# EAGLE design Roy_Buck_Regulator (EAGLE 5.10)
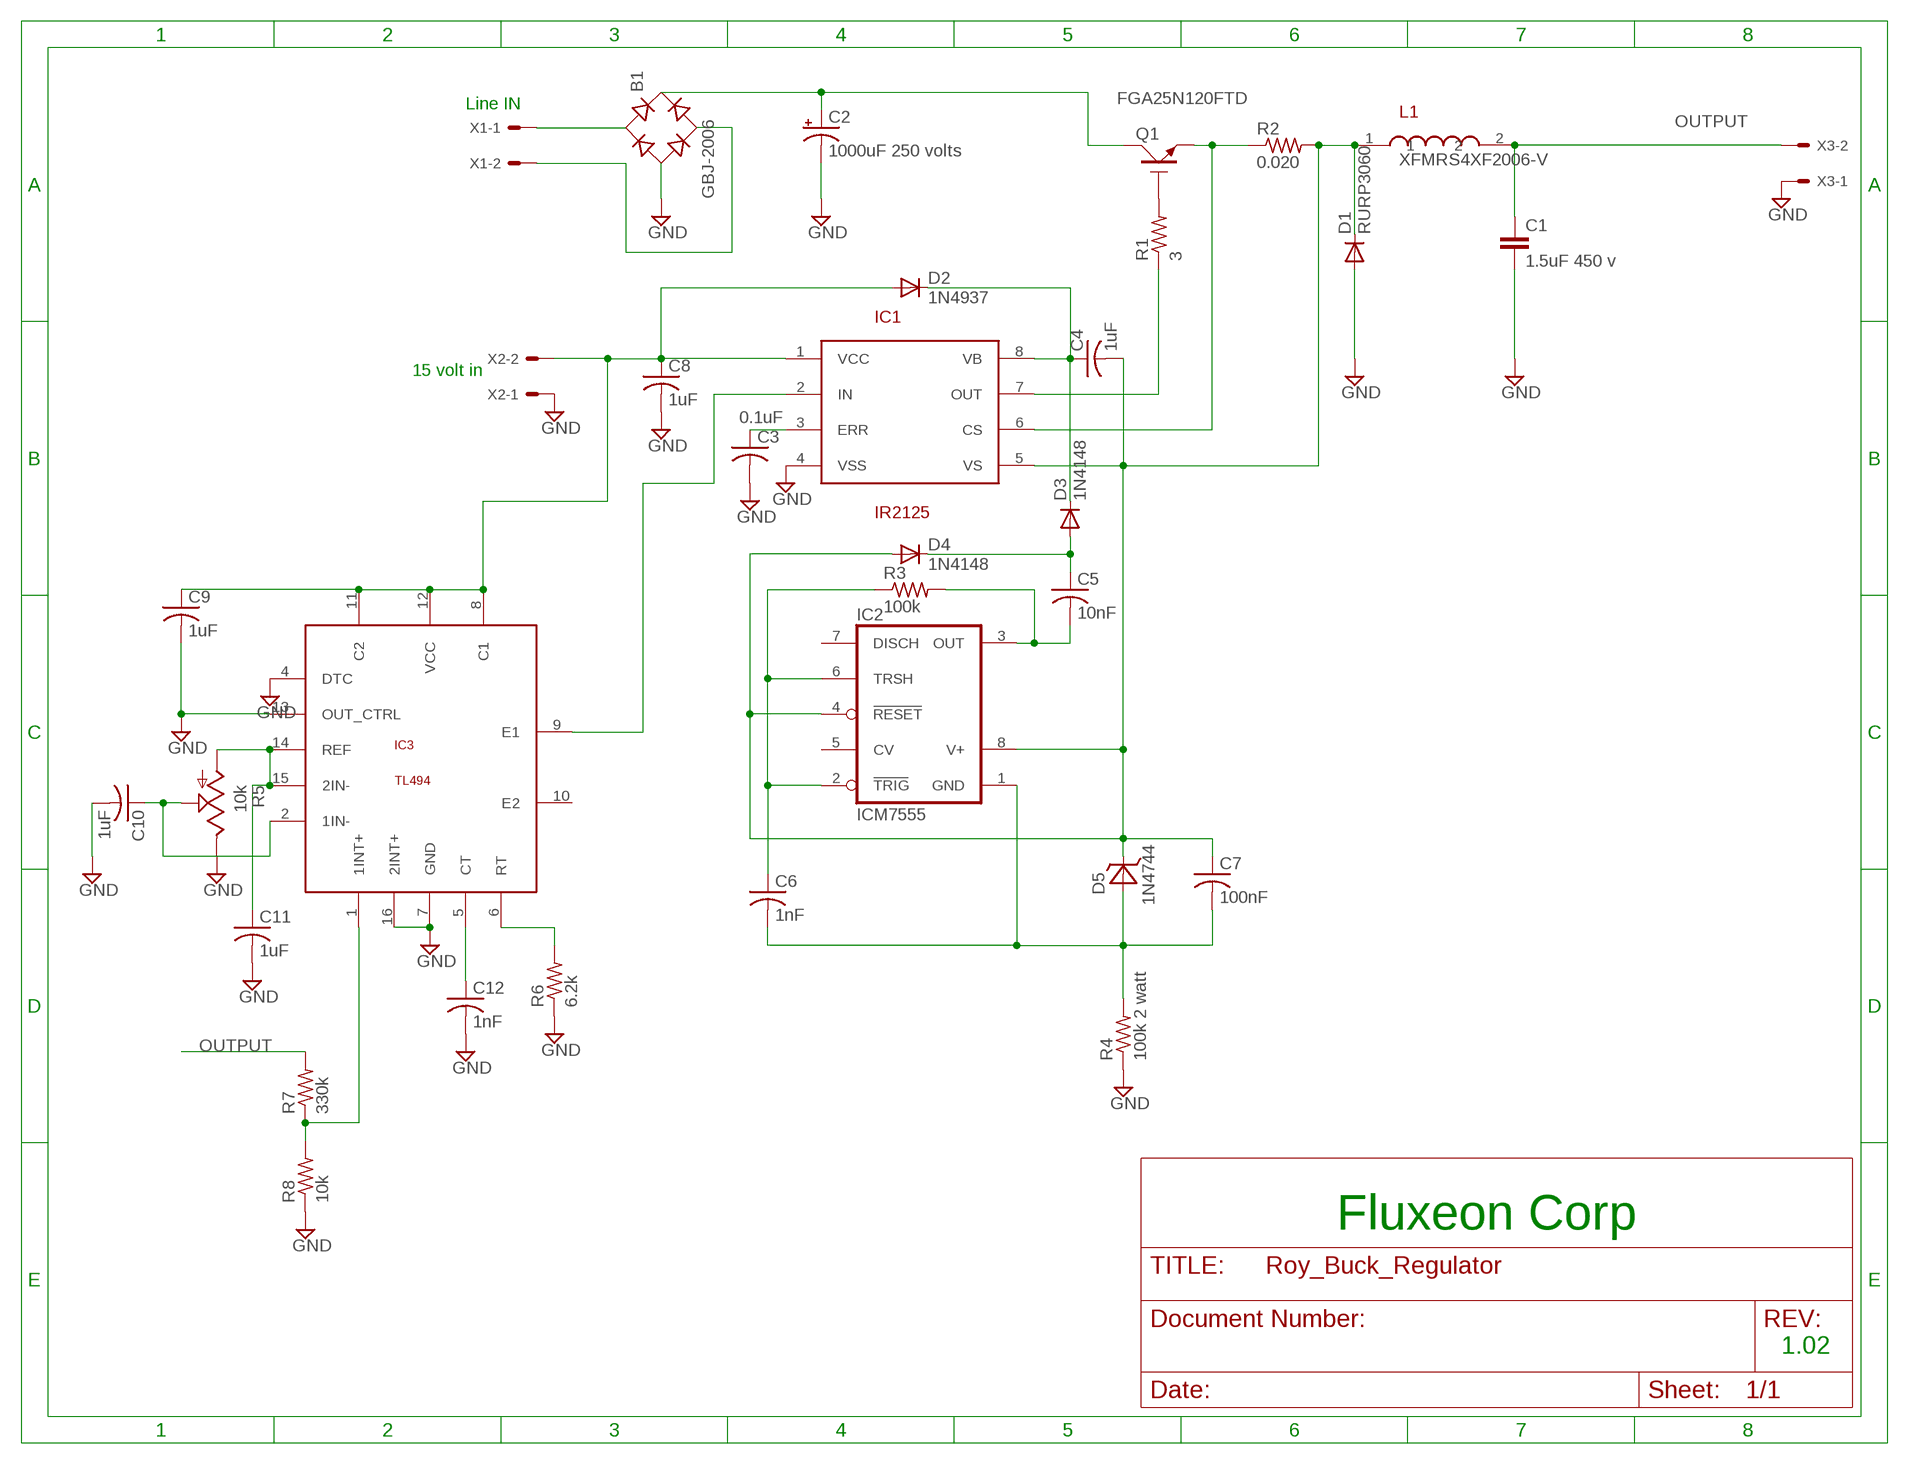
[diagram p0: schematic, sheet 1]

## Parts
B1  GBJ-2006  RECTIFIER-DSI32  [DSI32]
C1  1.5uF 450 v  CBLUE  [BLUE_1.5UF]
C2  1000uF 250 volts  CAP_1000UF_250VOLT  [ELECTRO_1_DIAMETER_10MM]
C3  0.1uF  C-US050-075X075  [C050-075X075]
C4  1uF  C-US050-075X075  [C050-075X075]
C5  10nF  C-US050-075X075  [C050-075X075]
C6  1nF  C-US050-075X075  [C050-075X075]
C7  100nF  C-US050-075X075  [C050-075X075]
C8  1uF  C-US050-075X075  [C050-075X075]
C9  1uF  C-US050-075X075  [C050-075X075]
C10  1uF  C-US050-075X075  [C050-075X075]
C11  1uF  C-US050-075X075  [C050-075X075]
C12  1nF  C-US050-075X075  [C050-075X075]
D1  RURP3060  RURP3060_DIODE"  [TO220ACS]
D2  1N4937  [DO41-10]
D3  1N4148  1N4148DO35-10  [DO35-10]
D4  1N4148  1N4148DO35-10  [DO35-10]
D5  1N4744  [DO41-10]
IC1  IR2125  IR2125_HI_SIDE_DRVRDIP8  [DIL08]
IC2  ICM7555  [DIL08]
IC3  TL494PDIP  [DIL16]
L1  XFMRS4XF2006-V  [TOROID_700]
Q1  FGA25N120FTD  [TO247BV]
R1  3  R-US_0617/17  [0617/17]
R2  0.020  R-US_0817/22  [CURRENT_SENSE_1.1_INCH_GRID]
R3  100k  R-US_0207/10  [0207/10]
R4  100k 2 watt  R-US_0414/15  [0414/15]
R5  10k  TRIM_US-10MM  [10MM_POT]
R6  6.2k  R-US_0207/10  [0207/10]
R7  330k  R-US_0207/10  [0207/10]
R8  10k  R-US_0207/10  [0207/10]
X1  KK-156-2  [KK-156-2]
X2  KK-156-2  [KK-156-2]
X3  KK-156-2  [KK-156-2]

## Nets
GND: B1.- C1.2 C2.2(-) C3.2 C8.2 C9.2 C10.2 C11.2 C12.2 D1.A IC1.4(VSS) IC3.4(DTC) IC3.7(GND) IC3.13(OUT_CTRL) IC3.16(2INT+) R4.1 R5.P$2(E) R6.1 R8.1 X2.1 X3.1
N$1: Q1.G R1.2
N$2: IC1.7(OUT) R1.1
N$3: C6.2 C7.2 D5.A IC2.1(GND) R4.2
N$4: IC3.1(1INT+) R7.1 R8.2
N$5 [high voltage]: B1.+ C2.1(+) Q1.D(C)
N$6 [high voltage]: B1.AC1 X1.1
N$7 [high voltage]: B1.AC2 X1.2
N$8 [high voltage]: IC1.6(CS) Q1.S(E) R2.1
N$9: C3.1 IC1.3(ERR)
N$10: C11.1 IC3.14(REF) IC3.15(2IN-) R5.P$3(A)
N$11: C4.1 D2.C D3.C IC1.8(VB)
N$14: C5.1 D3.A D4.C
N$15: C5.2 IC2.3(OUT) R3.2
N$16: C6.1 IC2.2(TRIG) IC2.6(TRSH) R3.1
N$17 [high voltage]: C4.2 C7.1 D1.C D4.A D5.C IC1.5(VS) IC2.4(RESET) IC2.8(V+) L1.1 R2.2
N$18: C10.1 IC3.2(1IN-) R5.P$1(S)
N$19: C12.1 IC3.5(CT)
N$20: IC3.6(RT) R6.2
N$21: IC1.2(IN) IC3.9(E1)
OUTPUT [high voltage]: C1.1 L1.2 R7.2 X3.2
VCC: C8.1 C9.1 D2.A IC1.1(VCC) IC3.8(C1) IC3.11(C2) IC3.12(VCC) X2.2
Unconnected: IC2.5(CV) IC2.7(DISCH) IC3.10(E2)

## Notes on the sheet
- Line IN
- 15 volt in
- Fluxeon Corp
- 1.02

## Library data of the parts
B1 = 00John:RECTIFIER-: Rectifier
C1 = 00John:C: CAPACITOR
C2 = 00John:CAP_1000UF_250VOLT: Electrolytic Capacitor, Snap-in
C3-C12 = 00John:C-US: CAPACITOR, American symbol
D1 = 00John:RURP3060_DIODE: 30 amp 600 volt ultrahigh speed soft recovery diode
D2 = 00John:1N4937: DIODE
D3 D4 = diode:1N4148: DIODE
D5 = 00John:1N4744: 1N4744 15 volt 1 watt Zener Diode
IC1 = 00John:IR2125_HI_SIDE_DRVR: IR2125 high side gate driver
IC2 = maxim:ICM7555: TIMER
IC3 = 00John:TL494: PWM Voltage Regulator/Controller
L1 = 00John:XFMRS4XF2006-V: Inductor, Toroidal, 200uH
Q1 = 00John:FGA25N120FTD: Fairchild FGA25n120 IGBT 1200 volts 50 amps TO-3P package
R1-R4 R6-R8 = 00John:R-US_: RESISTOR, American symbol
R5 = 00John:TRIM_US-: POTENTIOMETER
X1-X3 = 00John:KK-156-2: KK 156 HEADER

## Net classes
1 high voltage: width 2.54 mm, clearance 0.635 mm

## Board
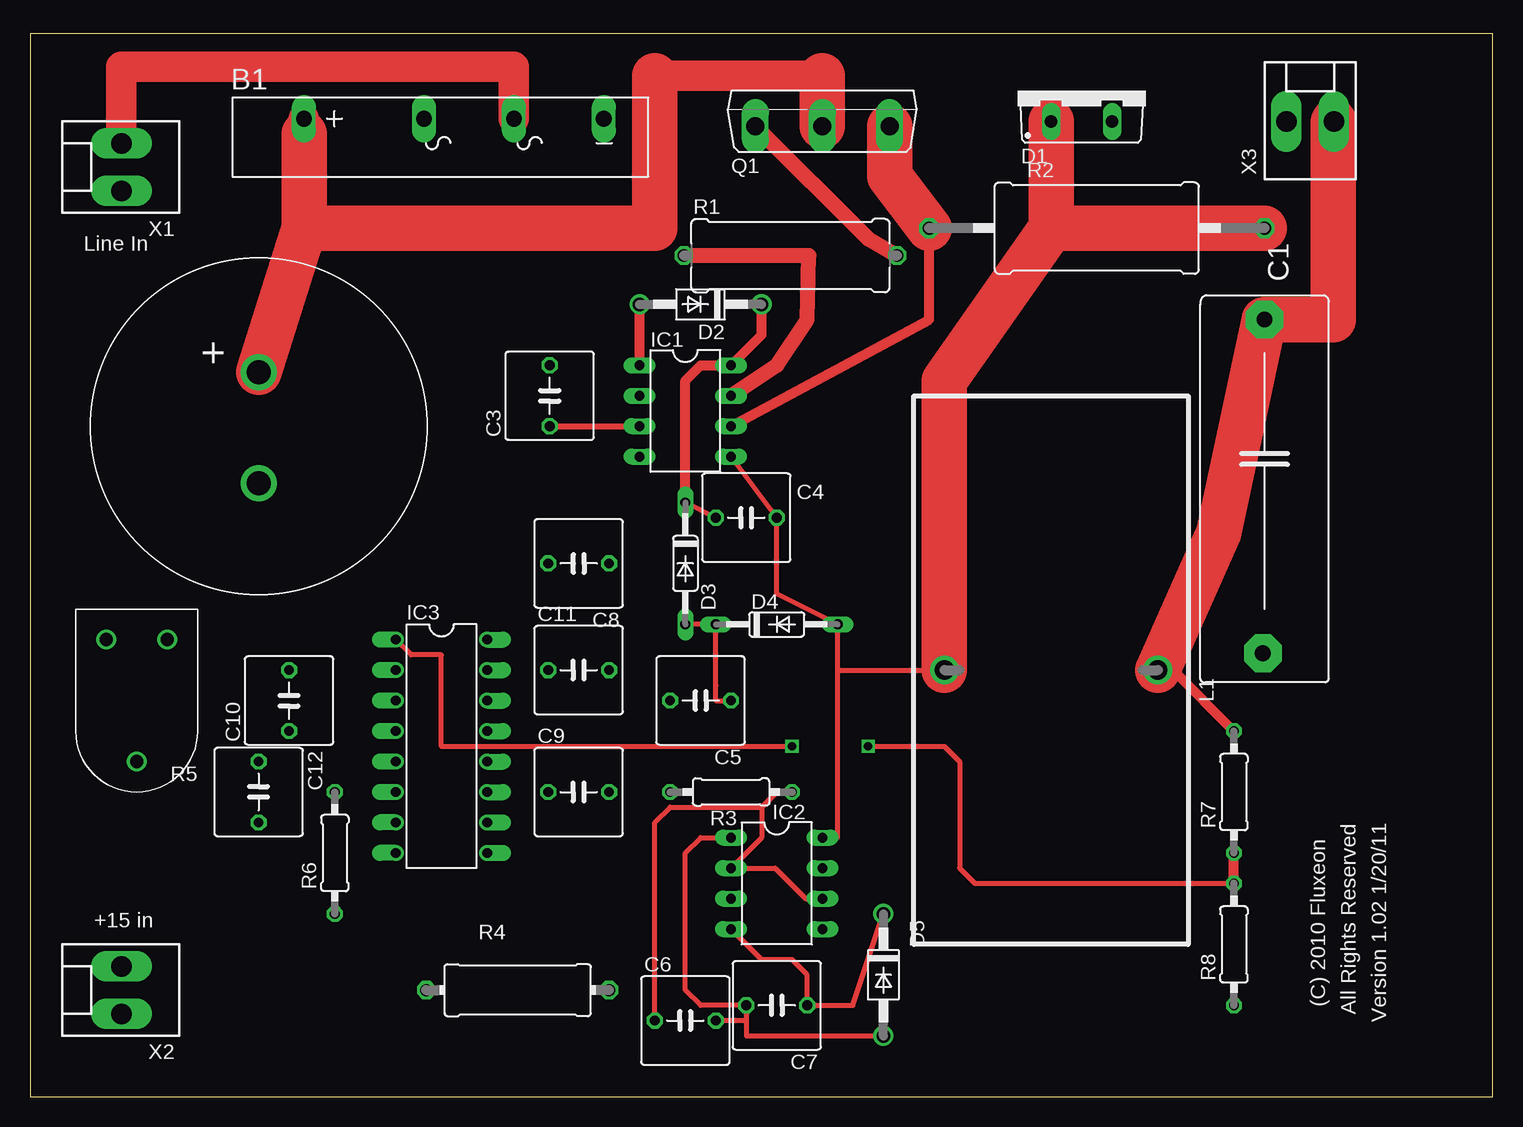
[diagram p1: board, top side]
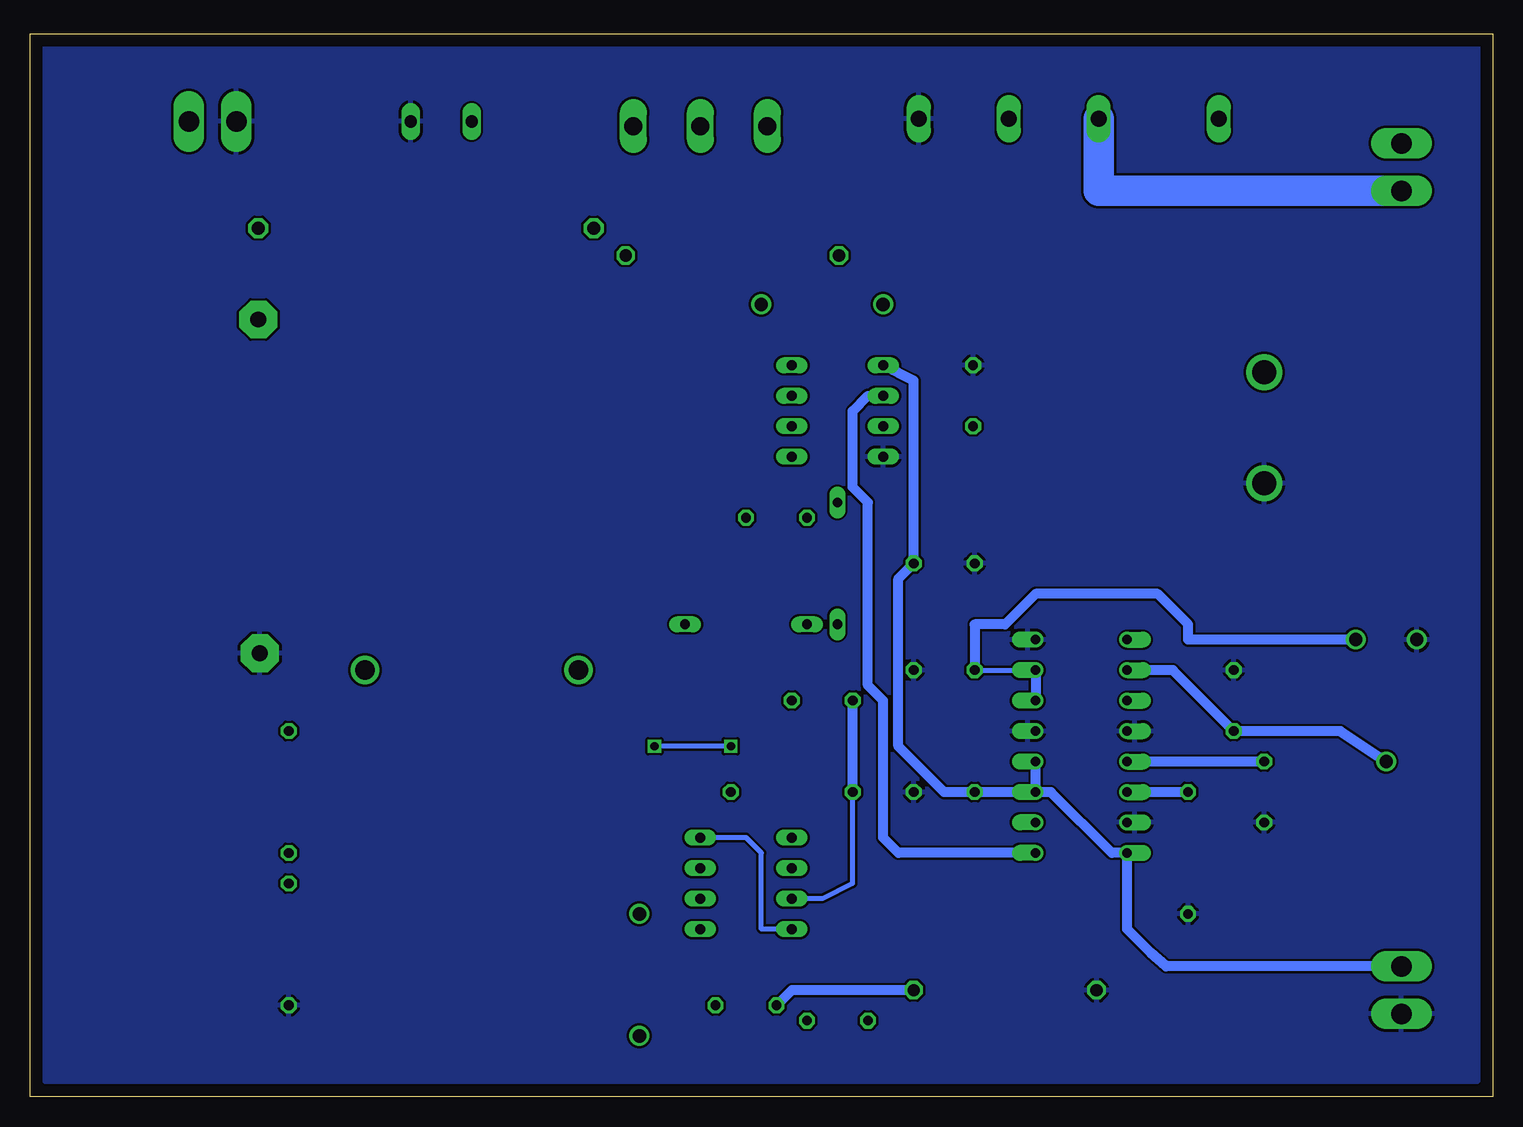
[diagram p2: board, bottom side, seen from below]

Size 121.9 x 88.57 mm. Coordinates in mm from the lower left corner, seen from the top.
Outline: 0,0 121.9,0 121.9,88.57 0,88.57 0,0
Copper layers (1*16): Top 0.035mm / dielectric 1.5mm / Bottom 0.035mm
Design rules "default": minimum track width 10mil, minimum drill 24mil, track to track 8mil, track to pad 8mil, pad to pad 8mil, via to via 8mil, smd to smd 8mil, copper to edge 40mil, drill to drill 8mil, minimum pad ring 10mil, minimum via ring 8mil, stop-mask expansion 4mil, vias tented up to drill 0mil, thermal gap 10mil

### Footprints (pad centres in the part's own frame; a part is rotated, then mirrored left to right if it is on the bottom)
DSI32 = drill 1.321 long: + -14,1.5; - 10.994,1.5; AC1 -3.992,1.5; AC2 3.501,1.5
BLUE_1.5UF = drill 1.321 pad 3.15 octagon: 1 0,0; 2 27.813,-0.127
ELECTRO_1_DIAMETER_10MM = drill 2 round: 1 4.492,0; 2 -4.746,0
C050-075X075 = drill 0.813 octagon: 1 -2.54,0; 2 2.54,0
TO220ACS = drill 1.016 long: A 2.54,-2.54; C -2.54,-2.54
DO41-10 = drill 1.118 round: A 5.08,0; C -5.08,0
DO35-10 = drill 0.813 long: A 5.08,0; C -5.08,0
DIL08 = drill 0.813 long: 1 -3.81,-3.81; 2 -1.27,-3.81; 3 1.27,-3.81; 4 3.81,-3.81; 5 3.81,3.81; 6 1.27,3.81; 7 -1.27,3.81; 8 -3.81,3.81
DIL16 = drill 0.813 offset: 1 -8.89,-3.81; 2 -6.35,-3.81; 3 -3.81,-3.81; 4 -1.27,-3.81; 5 1.27,-3.81; 6 3.81,-3.81; 7 6.35,-3.81; 8 8.89,-3.81; 9 8.89,3.81; 10 6.35,3.81; 11 3.81,3.81; 12 1.27,3.81; 13 -1.27,3.81; 14 -3.81,3.81; 15 -6.35,3.81; 16 -8.89,3.81
TOROID_700 = drill 1.6 round: 1 0,0; 2 17.78,0
TO247BV = drill 1.499 long: D 0,-2.921; G -5.588,-2.921; S 5.588,-2.921
0617/17 = drill 1.016 octagon: 1 -8.89,0; 2 8.89,0
CURRENT_SENSE_1.1_INCH_GRID = drill 1.1 octagon: 1 -11.43,0; 2 16.51,0
0207/10 = drill 0.813 octagon: 1 -5.08,0; 2 5.08,0
0414/15 = drill 1.016 octagon: 1 -7.62,0; 2 7.62,0
10MM_POT = drill 1.1 round: P$1 -5.08,0; P$2 5.08,2.54; P$3 5.08,-2.54
KK-156-2 = drill 1.7 pad 2.184 long: 1 -1.98,0; 2 1.98,0

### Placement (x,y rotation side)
B1  36.83,80.01 0 top
C1  102.87,64.77 270 top
C2  19.05,55.88 90 top
C3  43.31,58.42 90 top
C4  59.69,48.26 0 top
C5  55.88,33.02 180 top
C6  54.61,6.35 0 top
C7  62.23,7.62 180 top
C8  45.72,44.45 180 top
C9  45.72,25.4 0 top
C10  21.59,33.02 90 top
C11  45.72,35.56 0 top
C12  19.05,25.4 270 top
D1  87.63,83.82 0 top
D2  55.88,66.04 180 top
D3  54.61,44.45 270 top
D4  62.23,39.37 0 top
D5  71.12,10.16 270 top
IC1  54.61,57.15 270 top
IC2  62.23,17.78 270 top
IC3  34.29,29.21 270 top
L1  76.2,35.56 0 top
Q1  66.04,83.82 0 top
R1  63.37,70.1 0 top
R2  86.36,72.39 0 top
R3  58.42,25.4 180 top
R4  40.64,8.89 0 top
R5  8.89,33.02 90 top
R6  25.4,20.32 90 top
R7  100.33,25.4 90 top
R8  100.33,12.7 90 top
X1  7.62,77.47 90 top
X2  7.62,8.89 90 top
X3  106.68,81.28 0 top

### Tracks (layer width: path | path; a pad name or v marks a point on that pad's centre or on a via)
GND
  pour Bottom: 1.27,1.27 120.65,1.27 120.65,87.63 1.27,87.63
N$1
  Top 1.27: R1.2 69.85,71.5 Q1.G
N$2
  Top 1.27: IC1.7 62.23,60.96 64.77,64.77 64.9,70.1 R1.1
N$3
  Top 0.406: IC2.1 55.88,21.59 54.61,20.32 54.61,8.89 55.88,7.62 C7.2 59.69,6.35 | D5.A 59.69,5.08 59.69,6.35 | 59.69,6.35 C6.2
  Bottom 0.813: R4.2 58.42,8.89 C7.2
N$4  (via drill 0.7)
  Top 0.406: R8.2 78.74,17.78 77.47,19.05 77.47,27.94 76.2,29.21 v69.85,29.21 | v63.5,29.21 34.29,29.21 34.29,36.83 31.75,36.83 IC3.1
  Top 0.813: R8.2 R7.1
  Bottom 0.406: v63.5,29.21 v69.85,29.21
N$5
  Top 2.54: 22.86,80.24 B1.+ | 52.07,85.09 66.04,85.09
  Top 3.81: 22.86,72.39 22.86,80.24 | 66.04,85.09 Q1.D | 52.07,85.09 52.07,72.39 22.86,72.39 | C2.1 22.86,72.39
N$6
  Bottom 2.54: X1.1 32.84,75.49 B1.AC1
N$7
  Top 2.54: X1.2 7.62,85.85 40.33,85.85 B1.AC2
N$8
  Top 0.813: IC1.6 74.93,64.77 R2.1
  Top 3.81: Q1.S 71.63,76.71 R2.1
N$9
  Top 0.508: C3.1 IC1.3
N$10
  Bottom 0.406: C11.1 IC3.15
  Bottom 0.813: IC3.15 IC3.14 | R5.P$3 25.4,38.1 25.4,39.37 27.94,41.91 38.1,41.91 40.64,39.37 43.18,39.37 C11.1
N$11
  Top 0.406: D3.C C4.1
  Top 0.813: D2.C 60.96,63.5 IC1.8 55.88,60.96 54.61,59.69 D3.C
N$14
  Top 0.406: D3.A D4.C 57.15,34.29 57.15,33.02 C5.1
N$15
  Bottom 0.406: R3.2 53.34,17.78 55.88,16.51 IC2.3
  Bottom 0.813: R3.2 C5.2
N$16
  Top 0.406: C6.1 52.07,22.86 53.34,24.13 60.96,24.13 | 60.96,24.13 60.96,21.59 IC2.2 62.1,19.05 64.64,16.51 IC2.6 | R3.1 62.23,25.4 60.96,24.13
N$17
  Top 0.406: IC1.5 C4.2 62.23,41.91 D4.A 67.31,35.56 | 67.31,35.56 67.31,21.59 IC2.8 | IC2.4 60.96,11.43 63.5,11.43 64.77,10.16 C7.1 68.58,7.62 D5.C | 67.31,35.56 L1.1
  Top 3.81: 85.09,72.39 D1.C | 85.09,72.39 R2.2 | 85.09,72.39 76.2,59.69 L1.1
  Bottom 0.406: IC2.8 62.23,21.59 60.96,20.32 60.96,13.97 IC2.4
N$18
  Bottom 0.813: R5.P$1 12.7,30.48 C10.1 26.67,35.56 IC3.2
N$19
  Bottom 0.813: C12.1 IC3.5
N$20
  Bottom 0.813: R6.2 IC3.6
N$21
  Bottom 0.813: IC1.2 52.07,58.42 53.34,57.15 53.34,50.8 52.07,49.53 52.07,34.29 50.8,33.02 50.8,21.59 49.53,20.32 IC3.9
OUTPUT
  Top 0.813: L1.2 95.25,35.56 R7.2
  Top 3.81: L1.2 99.06,46.99 C1.1 108.58,64.77 108.58,81.21 X3.2
VCC
  Top 0.813: IC1.1 D2.A
  Bottom 0.813: IC1.1 48.26,59.69 C8.1 49.53,43.18 49.53,29.21 45.72,25.4 C9.1 IC3.11 | IC3.11 36.83,25.4 31.75,20.32 IC3.8 30.48,13.97 28.5,11.99 27.23,10.87 X2.2 | IC3.11 IC3.12

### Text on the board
tPlace: Line In | +15 in | (C) 2010 Fluxeon | All Rights Reserved | Version 1.02 1/20/11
